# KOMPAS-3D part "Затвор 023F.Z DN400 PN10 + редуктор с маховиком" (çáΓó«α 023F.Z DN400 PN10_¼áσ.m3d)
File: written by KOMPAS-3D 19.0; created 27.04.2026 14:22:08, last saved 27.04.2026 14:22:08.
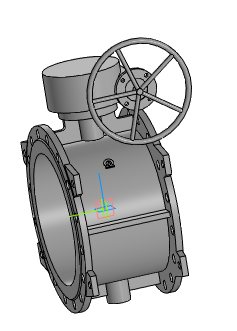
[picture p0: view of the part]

Document properties: Полное имя файла: ..\..\Затвор 023F.Z DN200-DN1600_с маховиком\Затвор 023F.Z DN400 PN10 + редуктор с маховиком.a3d

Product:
- Part/product: Затвор 023F.Z DN400 PN10 + редуктор с маховиком
    Масса: 188.46

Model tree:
1. Операция без истории:1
